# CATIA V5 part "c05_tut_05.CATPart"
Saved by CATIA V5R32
Part number: Part1
Bounding box of the stored display mesh (mm): x -12 to 12, y 0 to 257, z -11.818 to 11.818
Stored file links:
  D:\PROJECTS\Project 2022\CATIA V5 6R 2022\Resources\Tutorial Files\c05_catia_v5_6r2022_tut\c05_tut_05.CATPart
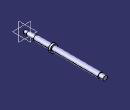
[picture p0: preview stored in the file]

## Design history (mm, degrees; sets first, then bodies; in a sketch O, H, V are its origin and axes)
Body1 (main body)
  Sketch1 on zx-plane, origin (0, 0, 0), H (-1, 0, 0), V (0, 0, 1)
    circle A1 centre (0, 0) radius 5
    circle A2 centre (0, 0) radius 6.5
    circle A3 centre (0, 0) radius 8
    circle A4 centre (0, 0) radius 7
    circle A5 centre (0, 0) radius 12
    radius A1 = 5
    radius A2 = 6.5
    radius A3 = 8
    radius A4 = 7
    radius A5 = 12
  MultiPad1: profile Sketch1, domains (length 93 / length -87; length 257 / length -35; length 241 / length -35; length 257 / length -11; length 257)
